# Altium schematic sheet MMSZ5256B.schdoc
size 127 x 101 mm
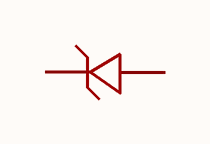
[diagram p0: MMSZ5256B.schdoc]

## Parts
ZD?  mmsz5256b  [SOD-123_L2.8-W1.8-LS3.7-RD]  (value not drawn)

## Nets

Not connected (* = marked no-connect by the designer): ZD? 1(K) 2(A)

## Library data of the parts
ZD? = mmsz5256b: 二极管配置:1个独立式;稳压值(标称值):30V;稳压值(范围):28.5V~31.5V;耗散功率(Pd):350mW;; Manufacturer: CJ(江苏长电/长晶); AddInBom: yes; ModelId: 7884390a25fb4c08947731ebfba7e3f8; ModelTransform: 144.8816,62.992,0,0,0,0,0,0,0; Diode Configuration: 1个独立式; Zener Voltage(Nom): 30V; Reverse Leakage Current (Ir): 100nA; Pd - Power Dissipation: 350mW; Impedance(Zzt): 49Ω; Impedance(Zzk): 600Ω; Operating Junction Temperature Range: -65℃~+150℃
